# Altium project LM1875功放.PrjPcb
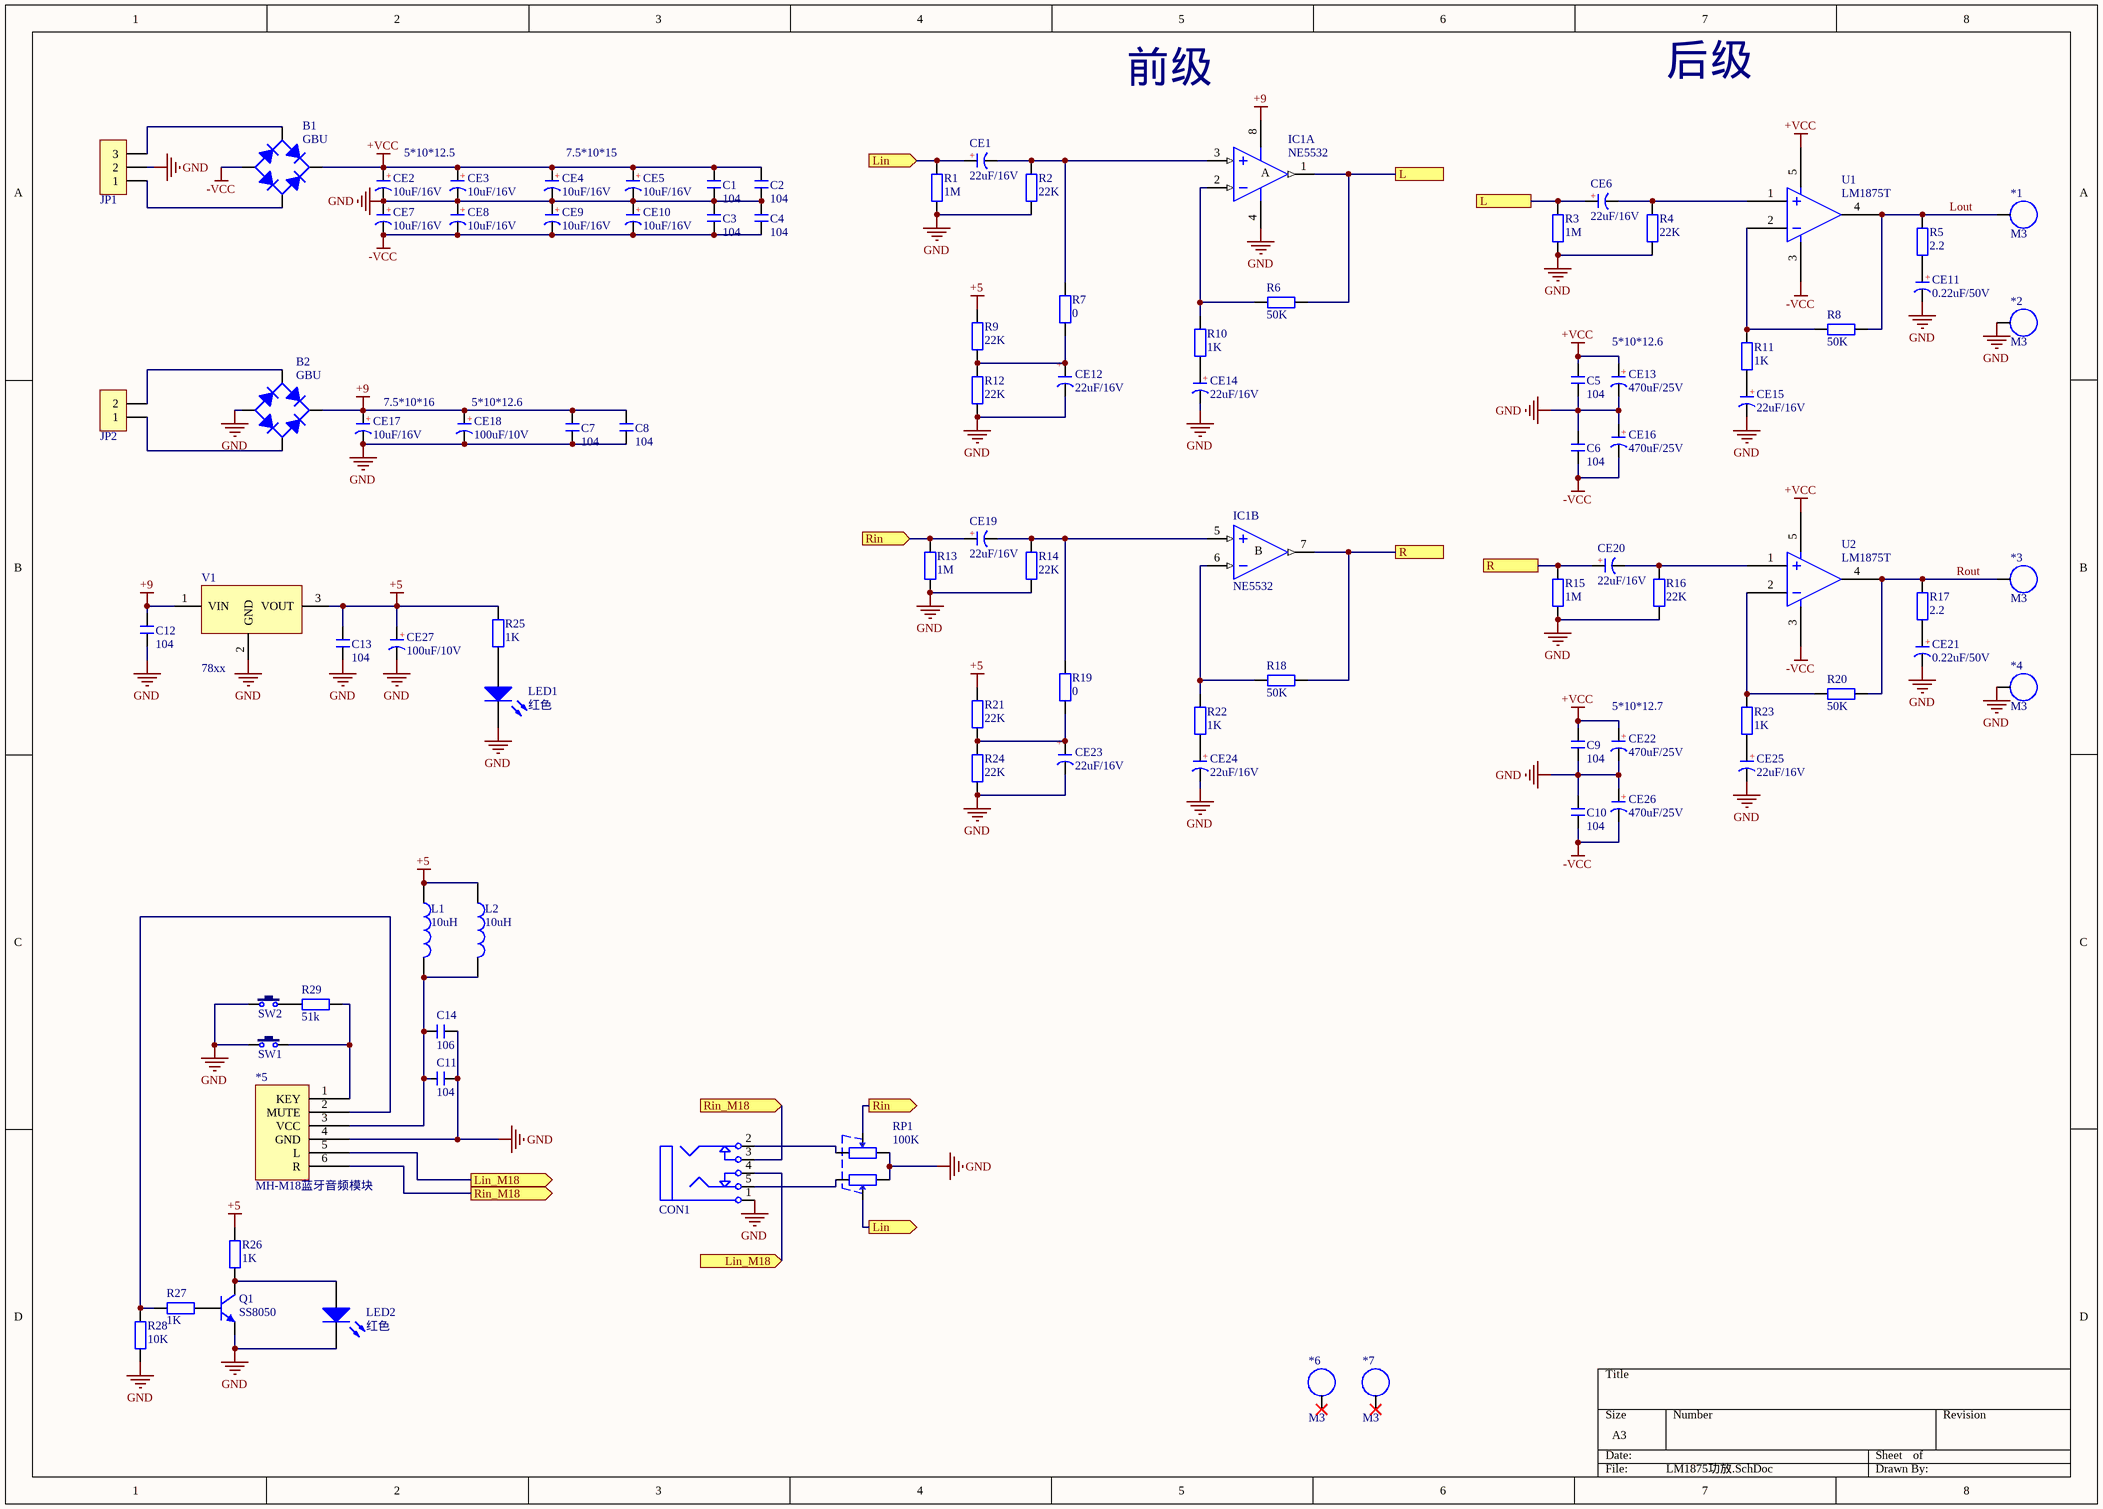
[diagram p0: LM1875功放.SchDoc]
1 sheet, 94 parts. Net scope: flat (ports and power ports of the same name join across sheets).
Board file: LM1875功放.PcbDoc

## Sheet LM1875功放.SchDoc
size A3; SheetNumber: 1; SheetTotal: 1

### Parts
*1  M3  [M3 125X200]
*2  M3  [M3 125X200]
*3  M3  [M3 125X200]
*4  M3  [M3 125X200]
*5  MH-M18蓝牙音频模块  [MH-M18蓝牙音频模块]
*6  M3  [M3 125X200]
*7  M3  [M3 125X200]
B1  GBU  [GBU]
B2  GBU  [GBU]
C1  104  [C 0603_L]
C2  104  [C 0603_L]
C3  104  [C 0603_L]
C4  104  [C 0603_L]
C5  104  [C 0603_L]
C6  104  [C 0603_L]
C7  104  [C 0603_L]
C8  104  [C 0603_L]
C9  104  [C 0603_L]
C10  104  [C 0603_L]
C11  104  [C 0603_L]
C12  104  [C 0603_L]
C13  104  [C 0603_L]
C14  106  [C 0603_L]
CE1  22uF/16V  [CAP 2.0*5*11]
CE2  10uF/16V  [CAP 5.0*10*12.5]
CE3  10uF/16V  [CAP 5.0*10*12.5]
CE4  10uF/16V  [CAP 7.5*16*25]
CE5  10uF/16V  [CAP 7.5*16*25]
CE6  22uF/16V  [CAP 2.0*5*11]
CE7  10uF/16V  [CAP 5.0*10*12.5]
CE8  10uF/16V  [CAP 5.0*10*12.5]
CE9  10uF/16V  [CAP 7.5*16*25]
CE10  10uF/16V  [CAP 7.5*16*25]
CE11  0.22uF/50V  [CAP 2.5*5*11]
CE12  22uF/16V  [CAP 2.0*5*11]
CE13  470uF/25V  [CAP 5.0*10*12.5]
CE14  22uF/16V  [CAP 2.0*5*11]
CE15  22uF/16V  [CAP 2.5*5*11]
CE16  470uF/25V  [CAP 5.0*10*12.5]
CE17  10uF/16V  [CAP 7.5*16*25]
CE18  100uF/10V  [CAP 3.5*8*11.5]
CE19  22uF/16V  [CAP 2.0*5*11]
CE20  22uF/16V  [CAP 2.0*5*11]
CE21  0.22uF/50V  [CAP 2.5*5*11]
CE22  470uF/25V  [CAP 5.0*10*12.5]
CE23  22uF/16V  [CAP 2.0*5*11]
CE24  22uF/16V  [CAP 2.0*5*11]
CE25  22uF/16V  [CAP 2.5*5*11]
CE26  470uF/25V  [CAP 5.0*10*12.5]
CE27  100uF/10V  [CAP 3.5*8*11.5]
CON1  3F07_BK  [3F07_PK]  (value not drawn)
IC1  NE5532  [SOP8_N]  (parts A,B of 2)
JP1  HDR-1X3  [KF301-5.0-3P]  (value not drawn)
JP2  HDR-1X2  [KF301-5.0-2P]  (value not drawn)
L1  10uH  [L 0603]
L2  10uH  [AL0410_V]
LED1  红色  [LED 3MM-B]
LED2  红色  [LED 3MM-B]
Q1  SS8050  [SOT23-3N]
R1  1M  [R 0603_L]
R2  22K  [R 0603_L]
R3  1M  [R 0603_L]
R4  22K  [R 0603_L]
R5  2.2  [RS 1W-V5]
R6  50K  [R 0603_L]
R7  0  [R 0603_L]
R8  50K  [R 0603_L]
R9  22K  [R 0603_L]
R10  1K  [R 0603_L]
R11  1K  [R 0603_L]
R12  22K  [R 0603_L]
R13  1M  [R 0603_L]
R14  22K  [R 0603_L]
R15  1M  [R 0603_L]
R16  22K  [R 0603_L]
R17  2.2  [RS 1W-V5]
R18  50K  [R 0603_L]
R19  0  [R 0603_L]
R20  50K  [R 0603_L]
R21  22K  [R 0603_L]
R22  1K  [R 0603_L]
R23  1K  [R 0603_L]
R24  22K  [R 0603_L]
R25  1K  [R 0603_L]
R26  1K  [R 0603_L]
R27  1K  [R 0603_L]
R28  10K  [R 0603_L]
R29  51k  [R 0603_L]
RP1  100K  [WH148-2-G15]
SW1  6x6x5  [TSW DIP-6*6*6_V]  (value not drawn)
SW2  6x6x5  [TSW DIP-6*6*6_V]  (value not drawn)
U1  LM1875T  [TO220-5]
U2  LM1875T  [TO220-5]
V1  78xx  [TO220A]

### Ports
L, Lin (in), Lin (out), Lin_M18 (in), Lin_M18 (out), R, Rin (in), Rin (out), Rin_M18 (in), Rin_M18 (out)

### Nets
+5: C13.1 CE27.1(A) L1.1 L2.1 R9.2 R21.2 R25.2 R26.1 V1.3(VOUT)
+9: B2.DC+ C7.1 C8.1 C12.1 CE17.1(A) CE18.1(A) IC1.8(V+) V1.1(VIN)
+VCC: B1.DC+ C1.1 C2.1 C5.1 C9.1 CE2.1(A) CE3.1(A) CE4.1(A) CE5.1(A) CE13.1(A) CE22.1(A) U1.5 U2.5
-VCC: B1.DC- C3.2 C4.2 C6.2 C10.2 CE7.2(K) CE8.2(K) CE9.2(K) CE10.2(K) CE16.2(K) CE26.2(K) U1.3 U2.3
GND: *2.1 *4.1 *5.4(GND) B2.DC- C1.2 C2.2 C3.1 C4.1 C5.2 C6.1 C7.2 C8.2 C9.2 C10.1 C11.1 C12.2 C13.2 C14.1 CE2.2(K) CE3.2(K) CE4.2(K) CE5.2(K) CE7.1(A) CE8.1(A) CE9.1(A) CE10.1(A) CE11.2(K) CE12.2(K) CE13.2(K) CE14.2(K) CE15.2(K) CE16.1(A) CE17.2(K) CE18.2(K) CE21.2(K) CE22.2(K) CE23.2(K) CE24.2(K) CE25.2(K) CE26.1(A) CE27.2(K) CON1.1 IC1.4(V-) JP1.2 LED1.2(K) LED2.2(K) Q1.2(E) R1.1 R2.1 R3.1 R4.1 R12.1 R13.1 R14.1 R15.1 R16.1 R24.1 R28.1 RP1.1 RP1.6 SW1.1 SW2.1 V1.2(GND)
Lout: *1.1 R5.2 R8.1 U1.4
Rout: *3.1 R17.2 R20.1 U2.4
Net*5_1: *5.1(KEY) R29.2 SW1.2
Net*5_2: *5.2(MUTE) R27.2 R28.2
Net*5_3: *5.3(VCC) C11.2 C14.2 L1.2 L2.2
Net*5_5: *5.5(L) CON1.4 ; port Lin_M18
Net*5_6: *5.6(R) CON1.3 ; port Rin_M18
NetB1_AC1: B1.AC1 JP1.3
NetB1_AC2: B1.AC2 JP1.1
NetB2_AC1: B2.AC1 JP2.2
NetB2_AC2: B2.AC2 JP2.1
NetCE1_1: CE1.1(A) R1.2 RP1.5 ; port Lin
NetCE1_2: CE1.2(K) IC1.3(IN+) R2.2 R7.2
NetCE6_1: CE6.1(A) IC1.1(OUT) R3.2 R6.2 ; port L
NetCE6_2: CE6.2(K) R4.2 U1.1
NetCE11_1: CE11.1(A) R5.1
NetCE12_1: CE12.1(A) R7.1 R9.1 R12.2
NetCE14_1: CE14.1(A) R10.2
NetCE15_1: CE15.1(A) R11.1
NetCE19_1: CE19.1(A) R13.2 RP1.2 ; port Rin
NetCE19_2: CE19.2(K) IC1.5(IN+) R14.2 R19.2
NetCE20_1: CE20.1(A) IC1.7(OUT) R15.2 R18.2 ; port R
NetCE20_2: CE20.2(K) R16.2 U2.1
NetCE21_1: CE21.1(A) R17.1
NetCE23_1: CE23.1(A) R19.1 R21.1 R24.2
NetCE24_1: CE24.1(A) R22.2
NetCE25_1: CE25.1(A) R23.1
NetCON1_2: CON1.2 RP1.3
NetCON1_5: CON1.5 RP1.4
NetIC1_2: IC1.2(IN-) R6.1 R10.1
NetIC1_6: IC1.6(IN-) R18.1 R22.1
NetLED1_1: LED1.1(A) R25.1
NetLED2_1: LED2.1(A) Q1.3(C) R26.2
NetQ1_1: Q1.1(B) R27.1
NetR8_2: R8.2 R11.2 U1.2
NetR20_2: R20.2 R23.2 U2.2
NetR29_1: R29.1 SW2.2

Not connected (* = marked no-connect by the designer): *6 1*; *7 1*

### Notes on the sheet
- 前级
- 后级
- 5*10*12.5
- 7.5*10*15
- 5*10*12.6
- 7.5*10*16
- (near CE18) 5*10*12.6
- 5*10*12.7

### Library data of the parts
*1-*4 *6 *7 = M3: 铜柱孔; 版权归属: 封装库来自淘宝 ID：黄晶宝石
B1 B2 = GBU: 1KV/10A整流桥; 版权归属: 封装库来自淘宝 ID：黄晶宝石
C1-C14 = C: 贴片电容; BOM名称: 无极性贴片电容; 淘宝ID: 封装库来自淘宝 ID：黄晶宝石
CE1-CE27 = CE: 直插电解电容; 淘宝ID: 封装库来自淘宝 ID：黄晶宝石
CON1 = 3F07: 3.5mm耳机插座; BOM名称: 耳机插座; 封装库来自淘宝卖家 ID：黄晶宝石: 其他店铺购入均为盗版，不享受售后技术支持服务，请立即申请退款
IC1 = NE5532: 双路低噪声音频运放; 版权归属: 封装库来自淘宝 ID：黄晶宝石
JP1 = Header 3: 3P接插件; 版权归属: 封装库来自淘宝 ID：黄晶宝石
JP2 = Header 2: 2P接插件; 版权归属: 封装库来自淘宝 ID：黄晶宝石
L1 = L: 小功率贴片电感; 淘宝ID: 封装库来自淘宝 ID：黄晶宝石; 封装库来自淘宝卖家 ID：黄晶宝石: 其他店铺购入均为盗版，不享受售后技术支持服务，请立即申请退款
L2 = L-AL: 色环电感; 淘宝ID: 封装库来自淘宝 ID：黄晶宝石
LED1 LED2 = LED-3MM: 直插3mm LED; BOM名称: 插件LED; 版权归属: 封装库来自淘宝 ID：黄晶宝石
Q1 = 8050-SMD: 高频放大-NPN型; 版权归属: 封装库来自淘宝 ID：黄晶宝石; 属性: 40V 1.5A 1W 100MHZ
R1-R4 R6-R16 R18-R29 = R: 贴片电阻; 版权归属: 来自淘宝 ID：黄晶宝石; 封装库来自淘宝卖家 ID：黄晶宝石: 其他店铺购入均为盗版，不享受售后技术支持服务，请立即申请退款
R5 R17 = R-S: 色环电阻; 版权归属: 封装库来自淘宝 ID：黄晶宝石
RP1 = RP-WH148: 双联电位器; BOM名称: 插件电位器; 版权归属: 封装库来自淘宝 ID：黄晶宝石
SW1 SW2 = TSW DIP-6x6_V: 侧按直插6x6轻触开关; 版权归属: 封装库来自淘宝 ID：黄晶宝石
V1 = 78xx: LM78XX系列线性稳压芯片; BOM名称: 线性稳压芯片; 淘宝ID: 封装库来自淘宝 ID：黄晶宝石; 技术支持，联系售后: 其他店铺购入均为盗版，不享受售后技术支持服务，请立即申请退款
